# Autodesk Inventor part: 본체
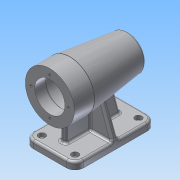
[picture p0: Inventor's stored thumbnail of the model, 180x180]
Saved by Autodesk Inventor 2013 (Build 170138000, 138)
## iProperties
Created: 2018-09
Part Number: 본체
Material: 알루미늄 6061
Document SubType Name: Modeling
Designer: Administrator
Density: 2.71 g/cm^3
Mass: 736.456 g
Surface Area: 667.699 cm^2
Volume: 271.755 cm^3
Author: Administrator
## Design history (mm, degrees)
sketch "스케치1"
  geometry: L1 (-56, 0)-(56, 0); L2 (-56, 0)-(-56, 34); L3 (-56, 34)-(-28, 34); L4 (-28, 34)-(52.27, 24.144); A1 r 80 centre (-24, 0) between (56, 0) and (52.27, 24.144); 2 further points
  constraints: 8 end point, 2 coincident, 2 perpendicular, 2 point on circle, 1 centre point, 1 horizontal, 1 midpoint, 1 point on line
  dimensions: "d0" = 112 distance of L1.start L1.end; "d2" = 68 diameter of L3 L1; "d3" = 80 radius of A1; "d4" = 7 deg angle of L4 L3; "d5" = 28 distance of L2.end L3.end
revolve "회전1" sketch "스케치1" stored, may be unused: angle "d6" = 90 deg
node "작업 평면1"
sketch "스케치2"
  geometry: L1 (-23, -56)-(23, -56); L2 (35, -44)-(35, 44); L3 (23, 56)-(-23, 56); L4 (-35, 44)-(-35, -44); A1 r 12 centre (-23, -44) between (-35, -44) and (-23, -56); A2 r 12 centre (23, -44) between (23, -56) and (35, -44); A3 r 12 centre (23, 44) between (35, 44) and (23, 56); A4 r 12 centre (-23, 44) between (-23, 56) and (-35, 44); 6 further points
  constraints: 8 end point, 8 point on circle, 8 tangent, 6 point on line, 4 centre point, 3 equal radius, 2 midpoint, 2 parallel, 1 horizontal, 1 horizontal alignment, 1 perpendicular, 1 vertical alignment
  dimensions: "d8" = 112 distance of point (-35, 56) point (-35, -56); "d10" = 70 distance of point (-35, -56) point (35, -56); "d11" = 12 radius of A1
extrude "돌출1" join sketch "스케치2" distance "d12" = 10; taper "d13" = 0 deg
sketch "스케치3"
  geometry: L1 (-35, -74)-(-35, -64) reference; L2 (-35, -64)-(35, -64) reference; L3 (35, -64)-(35, -74) reference; L4 (35, -74)-(-35, -74) reference; L5 (0, -20)-(0, -64); L6 (35, -64)-(16.049, -11.934); L7 (35, -64)-(0, -64); C1 r 30.562 at (0, 0) reference; A1 r 20 centre (0, 0) between (0, -20) and (16.049, -11.934); 1 further point
  constraints: 6 end point, 2 point on circle, 1 centre point, 1 coincident, 1 collinear, 1 midpoint
  dimensions: "d14" = 20 deg angle of L6 L3; "d15" = 90 deg angle of L5 L2
extrude "돌출2" join sketch "스케치3" stored distance "d16" = 8; taper "d17" = 0 deg
node "작업 평면2"
sketch "스케치4"
  geometry: L1 (56, 34)-(56, -34) reference; L2 (28, 34)-(56, 34) reference; L3 (-52.27, 24.144)-(28, 34) reference; L4 (-4, -30.071)-(-52.27, -24.144) reference; L5 (-4, -64)-(-4, -30.071) reference; L6 (-56, -64)-(-4, -64) reference; L7 (-56, -74)-(-56, -64) reference; L8 (56, -74)-(-56, -74) reference; L9 (56, -64)-(56, -74) reference; L10 (4, -64)-(56, -64) reference; L11 (4, -31.053)-(4, -64) reference; L12 (28, -34)-(4, -31.053) reference; L13 (56, -34)-(28, -34) reference; L14 (-25.942, -19)-(-38, -64); L15 (-38, -64)-(38, -64); L16 (38, -64)-(38, -19); L17 (-20, -19)-(38, -19); L18 (-20, -19)-(-25.942, -19); A1 r 80 centre (24, 0) between (-52.27, 24.144) and (-52.27, -24.144) reference; 1 further point
  constraints: 10 end point, 2 parallel, 2 point on line, 1 collinear, 1 perpendicular
  dimensions: "d19" = 105 deg angle of L14 L6; "d20" = 18 distance of L14.end L6.start; "d21" = 18 distance of L9.start L15.end; "d91" = 45 distance between parallel lines of L17 L15
extrude "돌출3" join sketch "스케치4" stored distance "d22" = 8; taper "d23" = 0 deg
node "작업 평면3"
sketch "스케치5"
  geometry: L1 (-56, 34)-(-28, 34) reference; L2 (-28, 34)-(52.27, 24.144) reference; L3 (52.27, -24.144)-(28.115, -27.11) reference; L4 (28.115, -27.11)-(38, -64) reference; L5 (38, -64)-(56, -64) reference; L6 (56, -64)-(56, -74) reference; L7 (56, -74)-(-56, -74) reference; L8 (-56, -74)-(-56, -64) reference; L9 (-56, -64)-(-38, -64) reference; L10 (-38, -64)-(-38, -34) reference; L11 (-38, -34)-(-56, -34) reference; L12 (-56, -34)-(-56, 34) reference; L13 (-56, 0)-(56, 0); L14 (-56, 0)-(-56, 21); L15 (-56, 21)-(-41, 21); L16 (-41, 21)-(-41, 21); L17 (-38, 24)-(10, 24); L18 (13, 21)-(13, 21); L19 (13, 21)-(24.7, 21); L20 (25, 20.7)-(25, 17.5); L21 (25, 17.5)-(42.7, 17.5); L22 (43, 17.2)-(43, 16); L23 (43, 16)-(46.7, 16); L24 (47, 15.7)-(47, 10.5); L25 (47, 10.5)-(47, 10.5); L26 (50, 7.5)-(50, 0); A1 r 80 centre (-24, 0) between (52.27, -24.144) and (52.27, 24.144) reference; A2 r 0.3 centre (24.7, 20.7) between (25, 20.7) and (24.7, 21); A3 r 0.3 centre (42.7, 17.2) between (43, 17.2) and (42.7, 17.5); A4 r 0.3 centre (46.7, 15.7) between (47, 15.7) and (46.7, 16); A5 r 3 centre (-38, 21) between (-38, 24) and (-41, 21); A6 r 3 centre (10, 21) between (13, 21) and (10, 24); A7 r 3 centre (47, 7.5) between (50, 7.5) and (47, 10.5); 7 further points
  constraints: 28 end point, 14 point on line, 13 point on circle, 12 tangent, 6 centre point, 6 parallel, 5 perpendicular, 3 equal radius, 1 collinear, 1 midpoint
  dimensions: "d25" = 42 diameter of L15 L13; "d27" = 15 distance of L14.end L15.end; "d28" = 48 diameter of L17 L13; "d29" = 54 distance of point (-41, 24) point (13, 24); "d30" = 42 diameter of L19 L13; "d31" = 12 distance of L18.end point (25, 21); "d32" = 18 distance of L20.end point (43, 17.5); "d33" = 35 diameter of L21 L13; "d34" = 4 distance of L22.end point (47, 16); "d35" = 32 diameter of L23 L13; "d36" = 3 distance of L24.end point (50, 10.5); "d37" = 21 diameter of L25 L13; "d38" = 0.3 radius of A2; "d39" = 3 radius of A5; "d40" = 3 radius of A7
revolve "회전2" sketch "스케치5" stored, may be unused: angle "d41" = 90 deg
sketch "스케치6"
  geometry: A1 r 12 centre (-23, -44) between (-35, -44) and (-23, -56) reference; A2 r 12 centre (23, -44) between (23, -56) and (35, -44) reference; 1 further point
hole "구멍1" sketch "스케치6" at (-23, -44), (23, -44) diameter "d42" = 5.5; stored, may be unused: countersink angle "d46" = 90 deg, drill point angle "d48" = 118 deg; dims "d43" = 6, "d44" = 9.5, "d45" = 5.4, "d47" = 8
sketch "스케치7"
  geometry: L1 (0, 88)-(0, 0) reference; L2 (0, -12)-(10, -12) reference; 2 further points
  constraints: 1 other
  dimensions: "d49" = 3 distance from line of point (3, 44) L1; "d50" = 56 distance from line of point (3, 44) L2
extrude "돌출4" join sketch "스케치7" distance "d51" = 0.5; taper "d52" = 0 deg
sketch "스케치8" dims "d53" = 52
  geometry: C1 r 21 at (0, 0) reference; C2 r 34 at (0, 0) reference; 2 further points
  constraints: 2 vertical alignment, 1 coincident, 2 other
hole "구멍2" sketch "스케치8" at (0, 26) diameter "d55" = 3.242; stored, may be unused: countersink angle "d59" = 90 deg, drill point angle "d61" = 118 deg; dims "d56" = 8, "d57" = 9.5, "d58" = 5.4, "d60" = 11
fillet "모깎기1" dims "d65" = 3
fillet "모깎기5" dims "d69" = 3
fillet "모깎기32" dims "d97" = 3
fillet "모깎기34" dims "d99" = 3
fillet "모깎기35" dims "d100" = 3
fillet "모깎기37" dims "d102" = 3
fillet "모깎기38" dims "d103" = 3
fillet "모깎기39" dims "d104" = 3
fillet "모깎기40" dims "d105" = 3
node "솔리드1"
mirror "대칭1"
mirror "대칭2"
pattern_circular "원형 패턴1" dims angle "d63" = 360 deg
node "절단 모서리 투영1"
node "절단 모서리 투영2"
node "절단 모서리 투영3"
other parameters: "d7" = -74, "d18" = 0, "d24" = 0
